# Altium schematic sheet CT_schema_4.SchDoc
size 517 x 390 mm
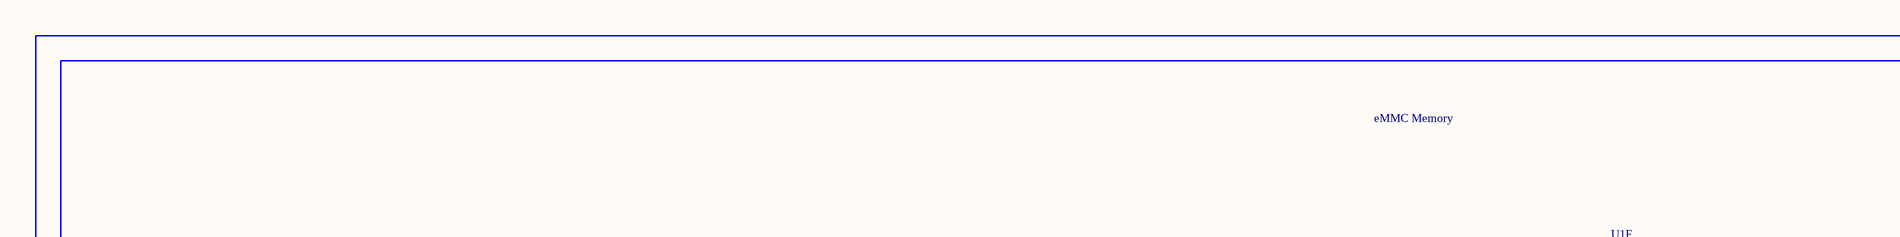
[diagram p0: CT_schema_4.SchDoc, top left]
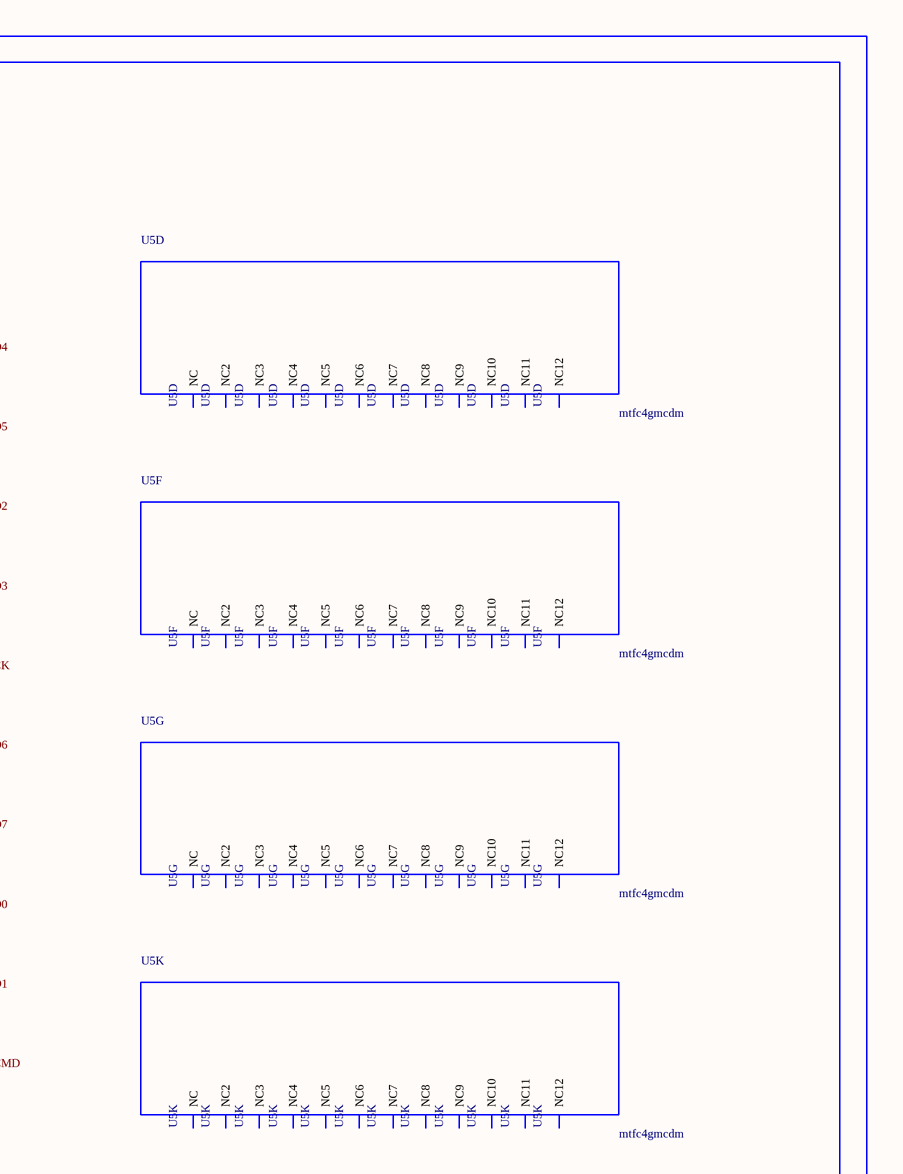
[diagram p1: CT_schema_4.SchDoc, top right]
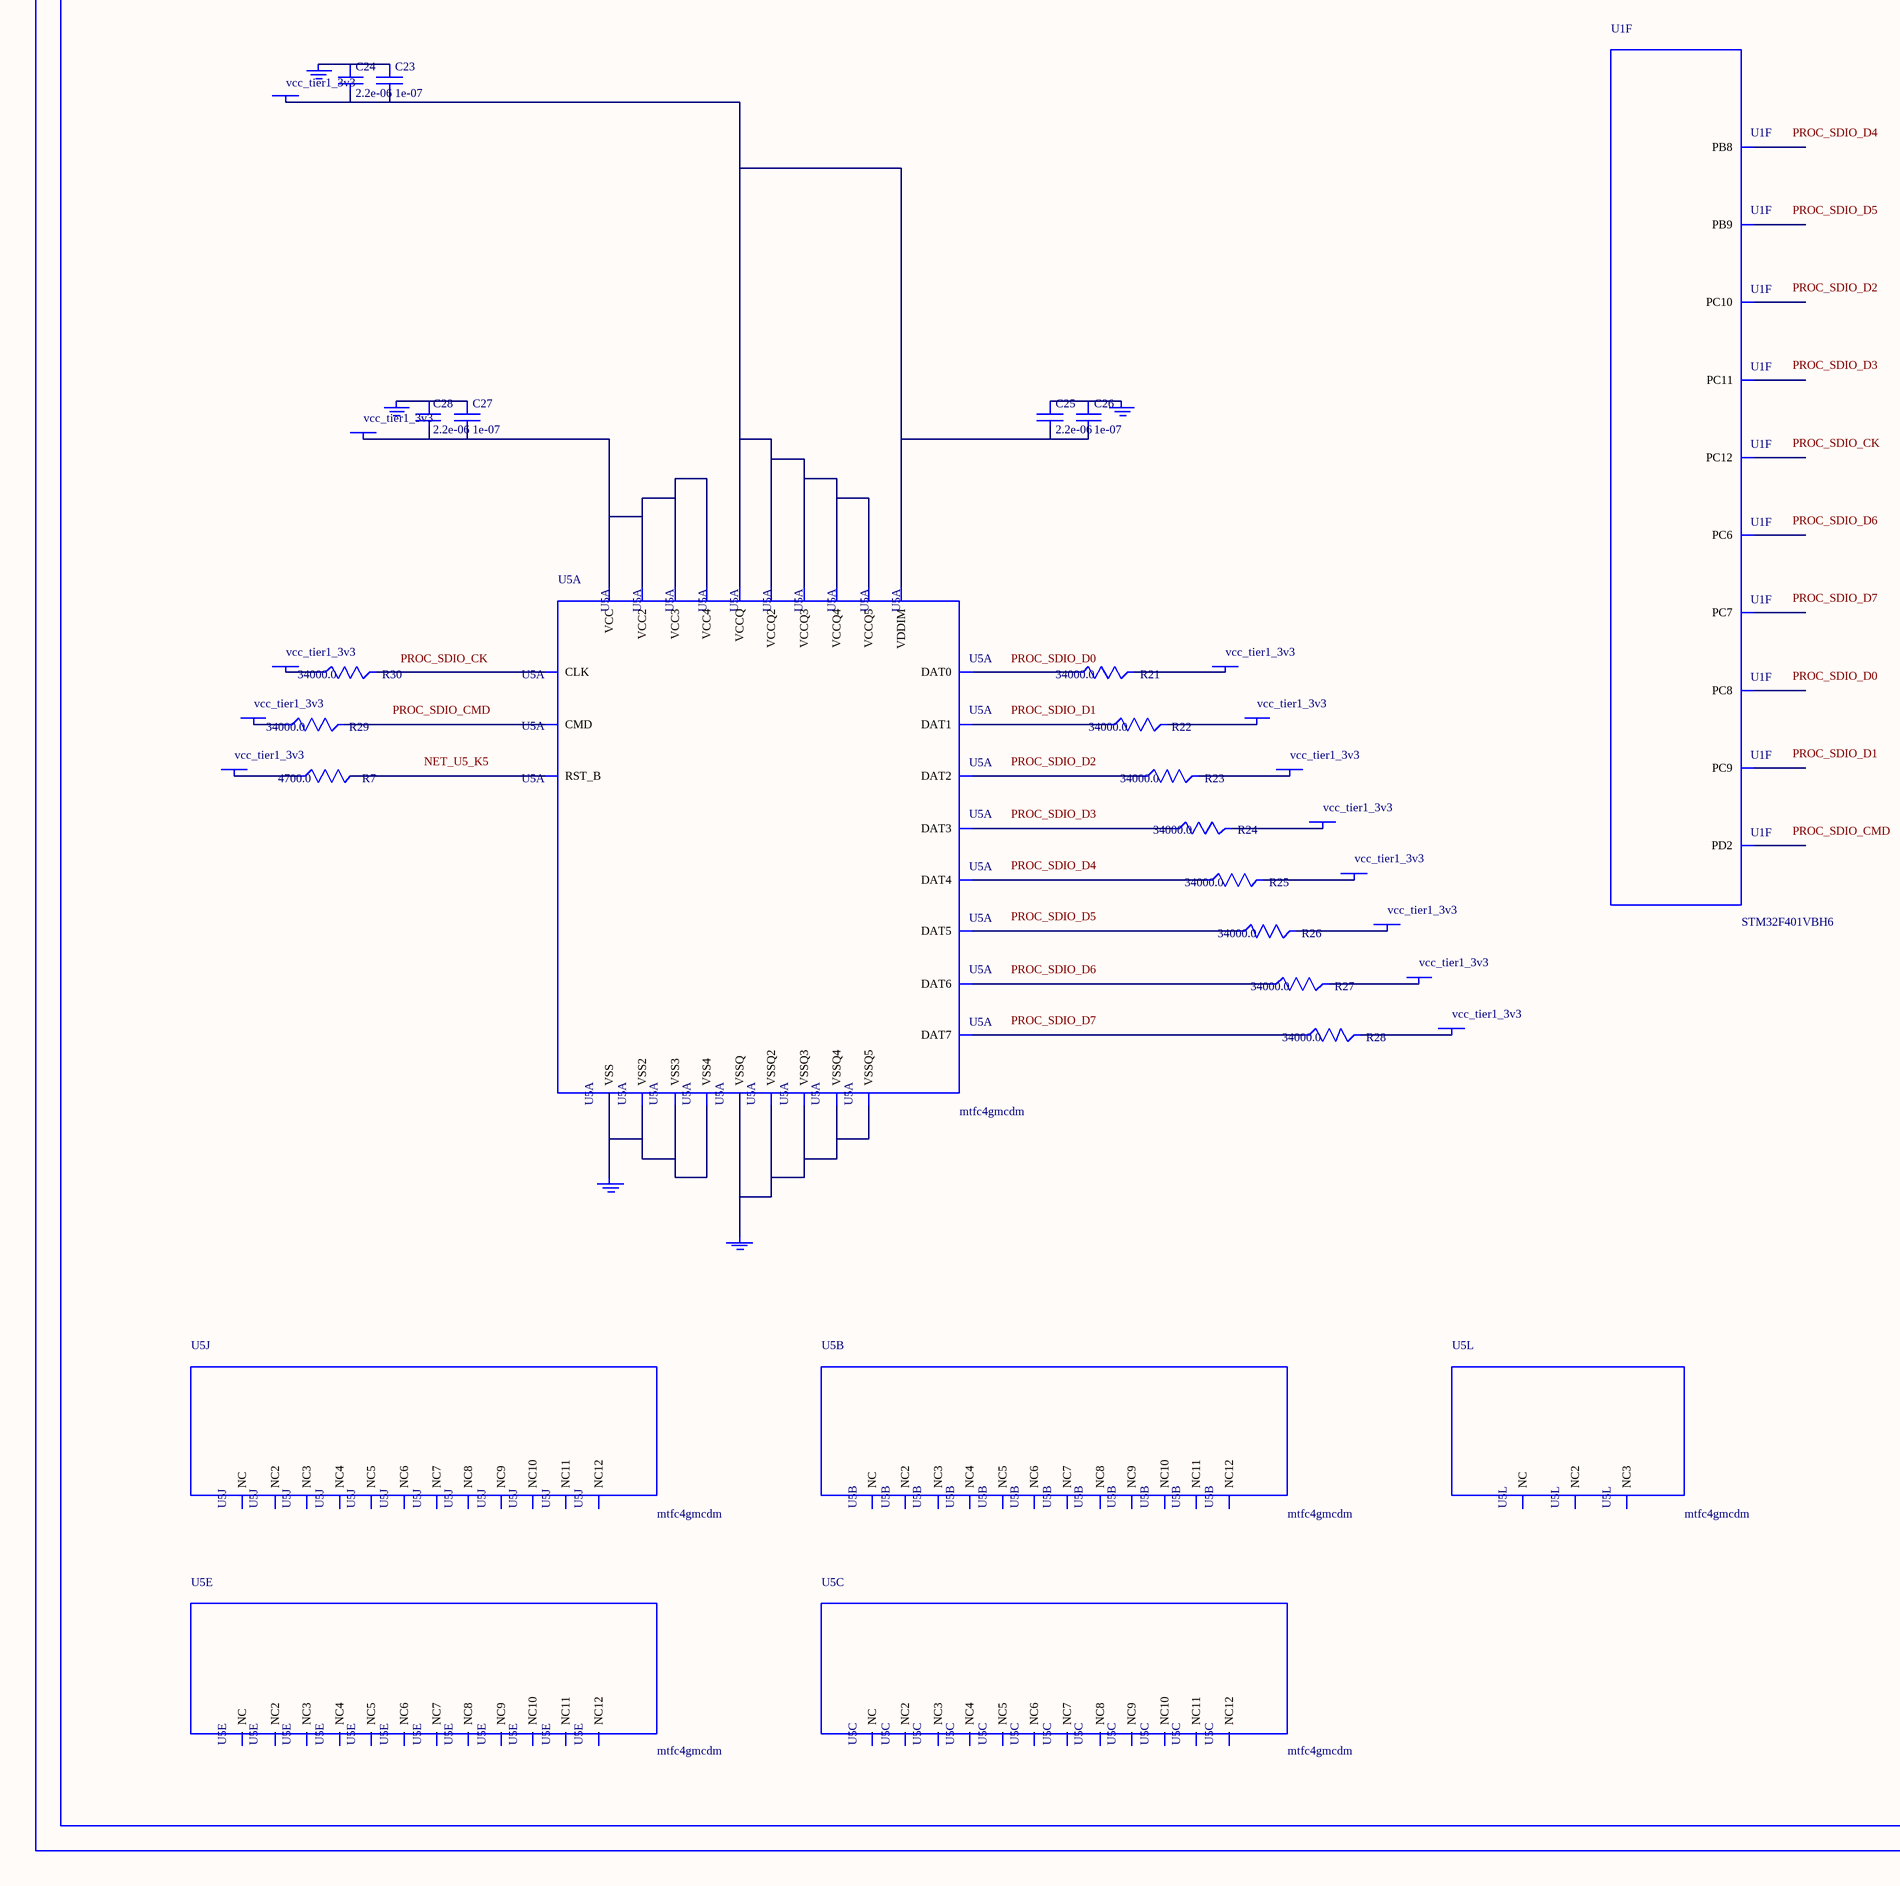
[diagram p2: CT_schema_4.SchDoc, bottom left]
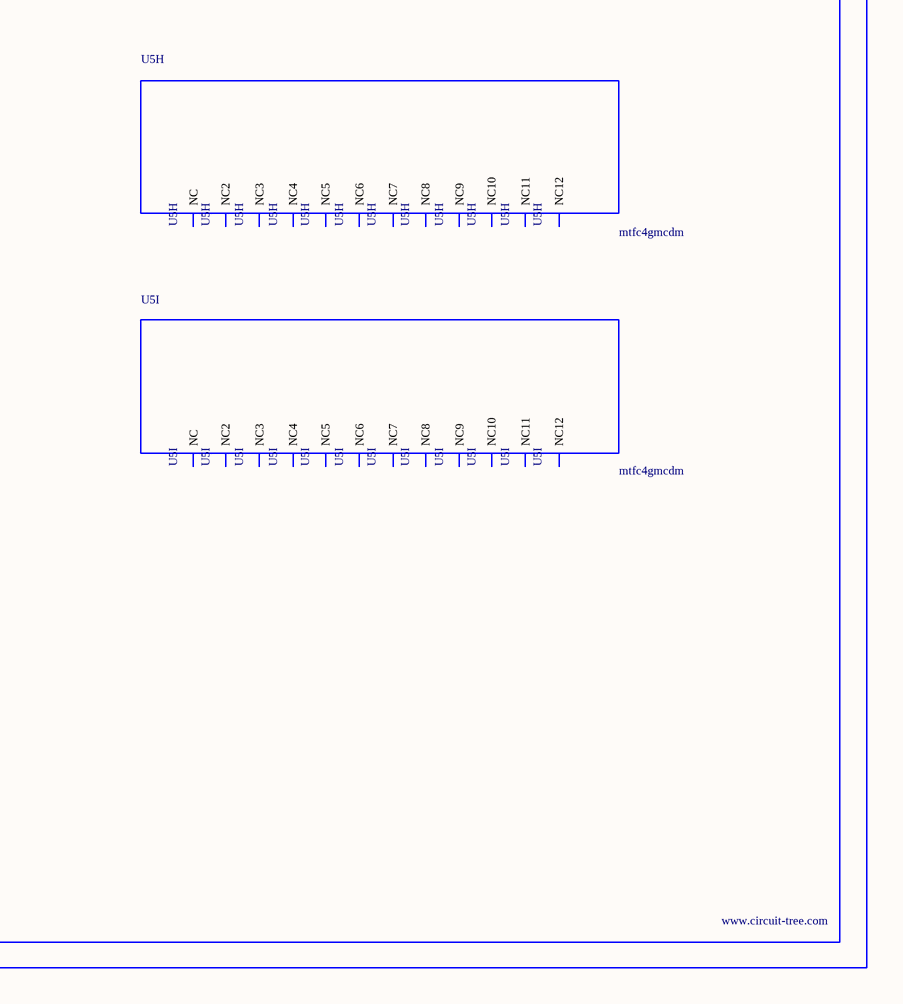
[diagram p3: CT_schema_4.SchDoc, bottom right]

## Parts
BORDER3  (no value)
C23  1e-07  [C0402]
C24  2.2e-06  [C0603]
C25  2.2e-06  [C0603]
C26  1e-07  [C0402]
C27  1e-07  [C0402]
C28  2.2e-06  [C0603]
GND_INSTANCE_3_0  (no value)
GND_INSTANCE_3_1  (no value)
GND_INSTANCE_3_2  (no value)
GND_INSTANCE_3_3  (no value)
GND_INSTANCE_3_4  (no value)
POWER_INSTANCE_3_0  vcc_tier1_3v3
POWER_INSTANCE_3_1  vcc_tier1_3v3
POWER_INSTANCE_3_2  vcc_tier1_3v3
POWER_INSTANCE_3_3  vcc_tier1_3v3
POWER_INSTANCE_3_4  vcc_tier1_3v3
POWER_INSTANCE_3_5  vcc_tier1_3v3
POWER_INSTANCE_3_6  vcc_tier1_3v3
POWER_INSTANCE_3_7  vcc_tier1_3v3
POWER_INSTANCE_3_8  vcc_tier1_3v3
POWER_INSTANCE_3_9  vcc_tier1_3v3
POWER_INSTANCE_3_10  vcc_tier1_3v3
POWER_INSTANCE_3_11  vcc_tier1_3v3
POWER_INSTANCE_3_12  vcc_tier1_3v3
R7  4700.0  [R0603]
R21  34000.0  [R0603]
R22  34000.0  [R0603]
R23  34000.0  [R0603]
R24  34000.0  [R0603]
R25  34000.0  [R0603]
R26  34000.0  [R0603]
R27  34000.0  [R0603]
R28  34000.0  [R0603]
R29  34000.0  [R0603]
R30  34000.0  [R0603]
U1  STM32F401VBH6  [UFBGA100]  (part F of 8)
U5  mtfc4gmcdm  [TFBGA-153]  (parts A,B,C,D,E,F,G,H,I,J,K,L of 12)

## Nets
NetC23_1: C23.1 C24.1 GND_INSTANCE_3_0.0(GND)
NetC23_2: C23.2 C24.2 C25.2 C26.2 POWER_INSTANCE_3_0.0(PWR) U5.C2(VDDIM) U5.C6(VCCQ) U5.M4(VCCQ2) U5.N4(VCCQ3) U5.P3(VCCQ4) U5.P5(VCCQ5)
NetC25_1: C25.1 C26.1 GND_INSTANCE_3_1.0(GND)
NetC27_1: C27.1 C28.1 GND_INSTANCE_3_2.0(GND)
NetC27_2: C27.2 C28.2 POWER_INSTANCE_3_1.0(PWR) U5.E6(VCC) U5.F5(VCC2) U5.J10(VCC3) U5.K9(VCC4)
NetGND_INSTANCE_3_3_0: GND_INSTANCE_3_3.0(GND) U5.E7(VSS) U5.G5(VSS2) U5.H10(VSS3) U5.K8(VSS4)
NetGND_INSTANCE_3_4_0: GND_INSTANCE_3_4.0(GND) U5.C4(VSSQ) U5.N2(VSSQ2) U5.N5(VSSQ3) U5.P4(VSSQ4) U5.P6(VSSQ5)
NetPOWER_INSTANCE_3_2_0: POWER_INSTANCE_3_2.0(PWR) R21.2
NetPOWER_INSTANCE_3_3_0: POWER_INSTANCE_3_3.0(PWR) R22.2
NetPOWER_INSTANCE_3_4_0: POWER_INSTANCE_3_4.0(PWR) R23.2
NetPOWER_INSTANCE_3_5_0: POWER_INSTANCE_3_5.0(PWR) R24.2
NetPOWER_INSTANCE_3_6_0: POWER_INSTANCE_3_6.0(PWR) R25.2
NetPOWER_INSTANCE_3_7_0: POWER_INSTANCE_3_7.0(PWR) R26.2
NetPOWER_INSTANCE_3_8_0: POWER_INSTANCE_3_8.0(PWR) R27.2
NetPOWER_INSTANCE_3_9_0: POWER_INSTANCE_3_9.0(PWR) R28.2
NetPOWER_INSTANCE_3_10_0: POWER_INSTANCE_3_10.0(PWR) R29.1
NetPOWER_INSTANCE_3_11_0: POWER_INSTANCE_3_11.0(PWR) R30.1
NetPOWER_INSTANCE_3_12_0: POWER_INSTANCE_3_12.0(PWR) R7.1
NetR7_2: R7.2 U5.K5(RST_B)
NetR21_1: R21.1 U5.A3(DAT0)
NetR22_1: R22.1 U5.A4(DAT1)
NetR23_1: R23.1 U5.A5(DAT2)
NetR24_1: R24.1 U5.B2(DAT3)
NetR25_1: R25.1 U5.B3(DAT4)
NetR26_1: R26.1 U5.B4(DAT5)
NetR27_1: R27.1 U5.B5(DAT6)
NetR28_1: R28.1 U5.B6(DAT7)
NetR29_2: R29.2 U5.M5(CMD)
NetR30_2: R30.2 U5.M6(CLK)

Not connected (* = marked no-connect by the designer): U1 A3(PB8) B3(PB9) B10(PC12) B11(PC10) C8(PD2) C10(PC11) D12(PC9) E10(PC8) E11(PC7) E12(PC6); U5 A1(NC) A2(NC7) A6(NC8) A7(NC9) A8(NC10) A9(NC11) A10(NC2) A11(NC3) A12(NC4) A13(NC5) A14(NC6) B1(NC12) B7(NC6) B8(NC7) B9(NC8) B10(NC) B11(NC2) B12(NC3) B13(NC4) B14(NC5) C1(NC9) C3(NC10) C5(NC11) C7(NC12) C8(NC6) C9(NC7) C10(NC) C11(NC2) C12(NC3) C13(NC4) C14(NC5) D1(NC8) D2(NC10) D3(NC11) D4(NC12) D12(NC9) D13(NC) D14(NC2) E1(NC3) E2(NC8) E3(NC9) E5(NC10) E8(NC11) E9(NC12) E10(NC4) E12(NC5) E13(NC6) E14(NC7) F1(NC) F2(NC6) F3(NC7) F10(NC2) F12(NC3) F13(NC4) F14(NC5) G1(NC8) G2(NC11) G3(NC12) G10(NC9) G12(NC10) G13(NC) G14(NC2) H1(NC3) H2(NC7) H3(NC8) H5(NC9) H12(NC4) H13(NC5) H14(NC6) J1(NC10) J2(NC11) J3(NC12) J5(NC4) J12(NC) J13(NC2) J14(NC3) K1(NC5) K2(NC9) K3(NC10) K6(NC11) K7(NC12) K10(NC6) K12(NC7) K13(NC8) K14(NC) L1(NC2) L2(NC6) L3(NC7) L12(NC3) L13(NC4) L14(NC5) M1(NC8) M2(NC9) M3(NC10) M7(NC11) M8(NC12) M9(NC6) M10(NC) M11(NC2) M12(NC3) M13(NC4) M14(NC5) N1(NC7) N3(NC8) N6(NC9) N7(NC10) N8(NC11) N9(NC12) N10(NC) N11(NC2) N12(NC3) N13(NC4) N14(NC5) P1(NC6) P2(NC9) P7(NC10) P8(NC11) P9(NC12) P10(NC7) P11(NC8) P12(NC) P13(NC2) P14(NC3)

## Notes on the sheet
- Labels drawn without touching a wire or pin: NET_U5_K5, PROC_SDIO_CK, PROC_SDIO_CMD, PROC_SDIO_D0, PROC_SDIO_D1, PROC_SDIO_D2, PROC_SDIO_D3, PROC_SDIO_D4, PROC_SDIO_D5, PROC_SDIO_D6, PROC_SDIO_D7

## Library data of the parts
BORDER3 = BORDER_PAGE3
C23 C26 C27 = C0402C104K3RACTU
C24 C25 C28 = C0603C225K8RACTU
GND_INSTANCE_3_0-GND_INSTANCE_3_4 = GND
POWER_INSTANCE_3_0-POWER_INSTANCE_3_12 = PWR
R7 = RC0603JR-074K7L
R21-R30 = ERA3ARB3402V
